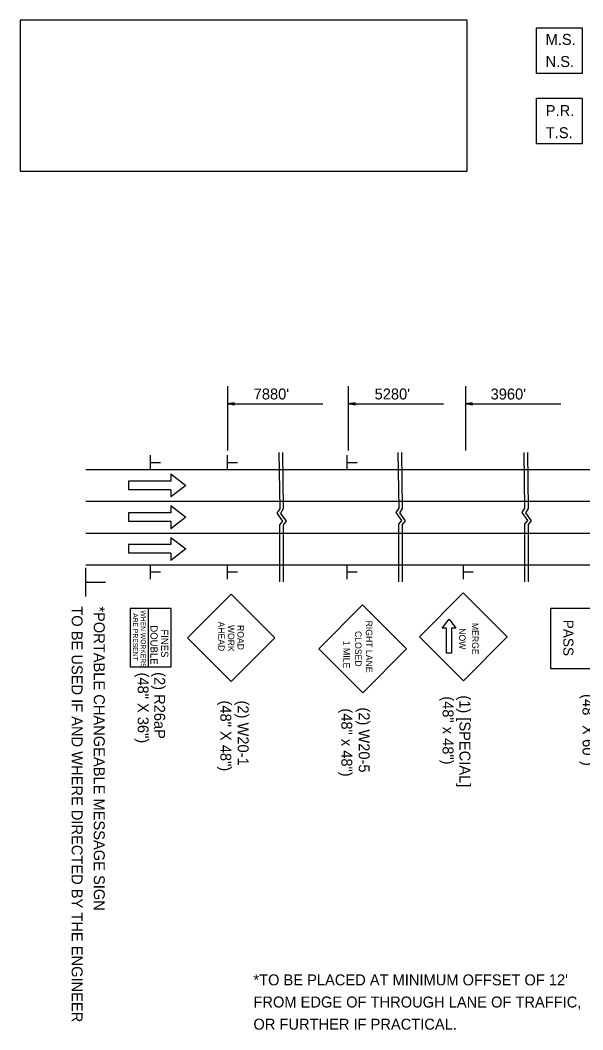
# Model space of a CAD drawing. Extents: x 1373848 to 1374003, y 380642 to 381248.
# Drawn here: x 1373851 to 1373881.8, y 381192.4 to 381247.7 of the extents above; entities that cross this region are included whole.
import ezdxf

# ---------------------------------------------------------------- set-up
doc = ezdxf.new("R2010")
doc.units = 0
for name, color, linetype in [('Default', 7, 'Continuous'), ('Level 3', 7, 'Continuous'), ('Level 8', 7, 'Continuous'), ('R_Draft', 7, 'Continuous')]:
    doc.layers.add(name, color=color, linetype=linetype)

msp = doc.modelspace()

# ---------------------------------------------------------------- linework, layer by layer
at = {"layer": 'Default'}
for p, q in [((1373862.377, 381227.612), (1373862.377, 381224.091)), ((1373869.001, 381227.612), (1373869.001, 381224.091)), ((1373875.417, 381227.612), (1373875.417, 381224.091)), ((1373862.752, 381226.689), (1373862.377, 381226.633)), ((1373862.377, 381226.633), (1373867.596, 381226.633)), ((1373862.752, 381226.577), (1373862.377, 381226.633)), ((1373862.752, 381226.68), (1373862.44, 381226.633)), ((1373862.752, 381226.586), (1373862.44, 381226.633)), ((1373862.752, 381226.67), (1373862.505, 381226.633)), ((1373862.752, 381226.596), (1373862.505, 381226.633)), ((1373862.752, 381226.661), (1373862.567, 381226.633)), ((1373862.752, 381226.605), (1373862.567, 381226.633)), ((1373862.752, 381226.651), (1373862.631, 381226.633)), ((1373862.752, 381226.615), (1373862.631, 381226.633)), ((1373862.752, 381226.642), (1373862.693, 381226.633)), ((1373862.752, 381226.624), (1373862.693, 381226.633)), ((1373862.752, 381226.577), (1373862.752, 381226.689)), ((1373869.376, 381226.689), (1373869.001, 381226.633)), ((1373869.001, 381226.633), (1373874.22, 381226.633)), ((1373869.376, 381226.577), (1373869.001, 381226.633)), ((1373869.376, 381226.68), (1373869.064, 381226.633)), ((1373869.376, 381226.586), (1373869.064, 381226.633)), ((1373869.376, 381226.67), (1373869.129, 381226.633)), ((1373869.376, 381226.596), (1373869.129, 381226.633)), ((1373869.376, 381226.661), (1373869.191, 381226.633)), ((1373869.376, 381226.605), (1373869.191, 381226.633)), ((1373869.376, 381226.651), (1373869.255, 381226.633)), ((1373869.376, 381226.615), (1373869.255, 381226.633)), ((1373869.376, 381226.642), (1373869.317, 381226.633)), ((1373869.376, 381226.624), (1373869.317, 381226.633)), ((1373869.376, 381226.577), (1373869.376, 381226.689)), ((1373875.792, 381226.689), (1373875.417, 381226.633)), ((1373875.417, 381226.633), (1373880.636, 381226.633)), ((1373875.792, 381226.577), (1373875.417, 381226.633)), ((1373875.792, 381226.68), (1373875.48, 381226.633)), ((1373875.792, 381226.586), (1373875.48, 381226.633)), ((1373875.792, 381226.67), (1373875.545, 381226.633)), ((1373875.792, 381226.596), (1373875.545, 381226.633)), ((1373875.792, 381226.661), (1373875.607, 381226.633)), ((1373875.792, 381226.605), (1373875.607, 381226.633)), ((1373875.792, 381226.651), (1373875.671, 381226.633)), ((1373875.792, 381226.615), (1373875.671, 381226.633)), ((1373875.792, 381226.642), (1373875.733, 381226.633)), ((1373875.792, 381226.624), (1373875.733, 381226.633)), ((1373875.792, 381226.577), (1373875.792, 381226.689)), ((1373858.171, 381223.041), (1373858.171, 381223.824)), ((1373862.377, 381223.041), (1373862.377, 381223.824)), ((1373868.94, 381223.041), (1373868.94, 381223.824)), ((1373854.616, 381223.041), (1373996.342, 381223.041)), ((1373858.182, 381223.43), (1373858.717, 381223.43)), ((1373862.389, 381223.43), (1373862.923, 381223.43)), ((1373868.951, 381223.43), (1373869.485, 381223.43)), ((1373859.277, 381222.409), (1373856.952, 381222.409)), ((1373856.952, 381222.409), (1373856.952, 381221.935)), ((1373859.277, 381222.804), (1373859.277, 381222.409)), ((1373859.277, 381222.804), (1373860.098, 381222.172)), ((1373859.277, 381221.935), (1373856.952, 381221.935)), ((1373860.098, 381222.172), (1373859.277, 381221.54)), ((1373859.277, 381221.935), (1373859.277, 381221.54)), ((1373854.616, 381221.303), (1373996.342, 381221.303)), ((1373859.277, 381221.066), (1373859.277, 381220.671)), ((1373859.277, 381221.066), (1373860.098, 381220.433)), ((1373859.277, 381220.671), (1373856.952, 381220.671)), ((1373856.952, 381220.671), (1373856.952, 381220.196)), ((1373859.277, 381220.196), (1373856.952, 381220.196)), ((1373860.098, 381220.433), (1373859.277, 381219.801)), ((1373859.277, 381220.196), (1373859.277, 381219.801)), ((1373854.616, 381219.564), (1373996.342, 381219.564)), ((1373859.277, 381219.327), (1373859.277, 381218.932)), ((1373859.277, 381219.327), (1373860.098, 381218.695)), ((1373859.277, 381218.932), (1373856.952, 381218.932)), ((1373856.952, 381218.932), (1373856.952, 381218.458)), ((1373860.098, 381218.695), (1373859.277, 381218.063)), ((1373859.277, 381218.458), (1373856.952, 381218.458)), ((1373859.277, 381218.458), (1373859.277, 381218.063)), ((1373854.616, 381217.826), (1373996.342, 381217.826)), ((1373854.616, 381216.089), (1373854.616, 381217.654)), ((1373858.171, 381217.043), (1373858.171, 381217.826)), ((1373858.182, 381217.432), (1373858.717, 381217.432)), ((1373862.377, 381217.043), (1373862.377, 381217.826)), ((1373862.389, 381217.432), (1373862.923, 381217.432)), ((1373868.94, 381217.043), (1373868.94, 381217.826)), ((1373868.951, 381217.432), (1373869.485, 381217.432)), ((1373875.302, 381217.043), (1373875.302, 381217.826)), ((1373875.314, 381217.432), (1373875.848, 381217.432)), ((1373854.639, 381216.867), (1373855.707, 381216.867)), ((1373872.895, 381213.879), (1373875.297, 381216.289)), ((1373877.705, 381213.887), (1373875.297, 381216.289)), ((1373860.2, 381213.835), (1373862.588, 381216.225)), ((1373864.979, 381213.835), (1373862.588, 381216.225)), ((1373867.379, 381213.216), (1373869.78, 381215.626)), ((1373872.188, 381213.224), (1373869.78, 381215.626)), ((1373874.146, 381214.364), (1373874.521, 381214.851)), ((1373874.521, 381214.851), (1373874.896, 381214.364)), ((1373874.38, 381214.364), (1373874.146, 381214.364)), ((1373874.38, 381212.985), (1373874.38, 381214.364)), ((1373874.661, 381214.364), (1373874.661, 381212.985)), ((1373874.896, 381214.364), (1373874.661, 381214.364)), ((1373862.588, 381211.444), (1373860.2, 381213.835)), ((1373862.588, 381211.444), (1373864.979, 381213.835)), ((1373875.305, 381211.477), (1373872.895, 381213.879)), ((1373875.305, 381211.477), (1373877.705, 381213.887)), ((1373869.789, 381210.814), (1373867.379, 381213.216)), ((1373869.789, 381210.814), (1373872.188, 381213.224)), ((1373874.661, 381212.985), (1373874.38, 381212.985))]:
    msp.add_line(p, q, dxfattribs=at)
for points in [[(1373879.309, 381244.737), (1373879.309, 381247.237), (1373881.809, 381247.237), (1373881.809, 381244.737)], [(1373879.309, 381240.872), (1373879.309, 381243.372), (1373881.809, 381243.372), (1373881.809, 381240.872)], [(1373884.283, 381212.131), (1373880.101, 381212.131), (1373880.101, 381215.449), (1373884.283, 381215.449)]]:
    msp.add_lwpolyline(points, close=True, dxfattribs=at)
for points in [[(1373865.194, 381223.977), (1373865.241, 381220.891), (1373865.078, 381220.65), (1373865.395, 381220.217), (1373865.228, 381220.017), (1373865.227, 381216.89)], [(1373865.393, 381223.977), (1373865.44, 381220.883), (1373865.278, 381220.642), (1373865.594, 381220.209), (1373865.428, 381220.009), (1373865.427, 381216.89)], [(1373871.712, 381223.977), (1373871.759, 381220.925), (1373871.596, 381220.683), (1373871.913, 381220.25), (1373871.746, 381220.05), (1373871.746, 381216.89)], [(1373871.912, 381223.977), (1373871.958, 381220.916), (1373871.796, 381220.675), (1373872.113, 381220.242), (1373871.946, 381220.042), (1373871.945, 381216.89)], [(1373878.613, 381223.977), (1373878.659, 381220.925), (1373878.497, 381220.683), (1373878.813, 381220.25), (1373878.647, 381220.05), (1373878.646, 381216.89)], [(1373878.813, 381223.977), (1373878.859, 381220.916), (1373878.697, 381220.675), (1373879.013, 381220.242), (1373878.846, 381220.042), (1373878.846, 381216.89)]]:
    msp.add_lwpolyline(points, dxfattribs=at)
at = {"layer": 'Level 3'}
msp.add_line((1373858.045, 381215.425), (1373858.045, 381212.244), dxfattribs=at)
msp.add_lwpolyline([(1373859.296, 381215.425), (1373857.046, 381215.425), (1373857.046, 381212.244), (1373859.296, 381212.244)], close=True, dxfattribs=at)
at = {"layer": 'R_Draft'}
msp.add_lwpolyline([(1373851.027, 381239.388), (1373875.515, 381239.388), (1373875.515, 381247.651), (1373851.027, 381247.651)], close=True, dxfattribs=at)

# ---------------------------------------------------------------- texts
at = {"layer": 'Default'}
for s, height, rotation, p in [('M.S.', 0.6, 360, (1373879.807, 381246.298)), ('N.S.', 0.6, 360, (1373879.807, 381245.085)), ('P.R.', 0.6, 360, (1373879.818, 381242.402)), ('T.S.', 0.6, 360, (1373879.818, 381241.189)), ('TO BE USED IF AND WHERE DIRECTED BY THE ENGINEER', 0.6, 270, (1373853.845, 381215.551)), ('*PORTABLE CHANGEABLE MESSAGE SIGN', 0.6, 270, (1373855.058, 381215.551)), (' AHEAD', 0.3522, 270.0006, (1373861.872, 381214.847)), ('RIGHT LANE', 0.3544, 270.1004, (1373869.959, 381214.769)), ('MERGE', 0.3544, 270.1004, (1373875.776, 381214.645)), ('PASS', 0.5566, 270, (1373880.775, 381214.816)), ('WORK', 0.352, 270, (1373862.401, 381214.532)), ('ROAD', 0.3521, 270.0004, (1373862.929, 381214.525)), ('CLOSED', 0.3543, 270.1003, (1373869.369, 381214.198)), ('NOW', 0.3543, 270.1003, (1373875.067, 381214.352)), ('1 MILE', 0.3567, 270.0006, (1373868.728, 381213.667)), ('(48" X 48")', 0.6, 270, (1373861.989, 381210.393)), ('(2) W20-1', 0.6, 270, (1373862.94, 381210.393)), ('(48" x 48")', 0.6, 270, (1373874.162, 381210.624)), ('(1) [SPECIAL]', 0.6, 270, (1373875.087, 381210.678)), ('(48" X 60")', 0.61, 270, (1373881.829, 381210.75)), ('(48" x 48")', 0.6, 270, (1373868.615, 381209.961)), ('(2) W20-5', 0.6, 270, (1373869.57, 381210.015)), ("*TO BE PLACED AT MINIMUM OFFSET OF 12'", 0.6, 360, (1373863.802, 381194.795)), ('FROM EDGE OF THROUGH LANE OF TRAFFIC,', 0.6, 360, (1373863.802, 381193.582)), ('OR FURTHER IF PRACTICAL.', 0.6, 360, (1373863.802, 381192.369))]:
    msp.add_text(s, height=height, rotation=rotation, dxfattribs=at).set_placement(p)
for s, p in [("7880'", (1373863.817, 381226.88)), ("5280'", (1373870.441, 381226.88)), ("3960'", (1373876.795, 381226.878))]:
    msp.add_text(s, height=0.6, dxfattribs=at).set_placement(p)
at = {"layer": 'Level 8'}
for s, height, p in [('ARE PRESENT', 0.26717, (1373857.205, 381215.175)), ('WHEN WORKERS', 0.26713, (1373857.632, 381215.329)), ('DOUBLE', 0.39, (1373858.164, 381214.509)), ('FINES', 0.39, (1373858.748, 381214.288)), ('(48" X 36")', 0.59965, (1373857.461, 381211.925)), ('(2) R26aP', 0.5997, (1373858.367, 381211.946))]:
    msp.add_text(s, height=height, rotation=270, dxfattribs=at).set_placement(p)

doc.saveas('drawing.dxf')
